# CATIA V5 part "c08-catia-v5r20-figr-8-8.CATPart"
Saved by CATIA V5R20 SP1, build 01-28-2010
Part number: Part1
Bounding box of the stored display mesh (mm): x 4.549 to 89.781, y -52.238 to 26.36, z 54 to 147.773
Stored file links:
  D:\v5_r20\psrt_files_downloaded\c08-catia-v5r20-prt\c08-catia-v5r20-figr-8-8.CATPart
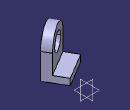
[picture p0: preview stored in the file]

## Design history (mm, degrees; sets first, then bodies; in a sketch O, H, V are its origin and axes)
Body1 (main body)
  Sketch1 on yz-plane, origin (0, 0, 0), H (0, 1, 0), V (0, 0, 1)
    point P1 (-104.4861, 0)
    line L1 (-104.4861, 0) -> (-104.4861, 44.267)
    arc A1 centre (-69.7903, 44.267) radius 34.6958 from (-104.4861, 44.267) to (-35.0946, 44.267) cw
    line L2 (-35.0946, 44.267) -> (-35.0946, 0)
    point P5 (-35.0946, 0)
    line L3 (-35.0946, 0) -> (-104.4861, 0)
    circle A2 centre (-69.7903, 44.267) radius 19.5413
    coincidence: P1 H, P5 H
    vertical: L1 V
    tangency: A1 L1, L2 A1
    horizontal: L3 H
  Pad1: profile Sketch1, direction (1, 0, 0), length 20
  Sketch2 on face of Pad1, origin (0, 0, 0), H (0, -1, 0), V (0, 0, 1)
    point P1 (35.0946, 0)
    line L1 (35.0946, 0) -> (104.4861, 0)
    line L2 (104.4861, 0) -> (104.4861, -15)
    line L3 (104.4861, -15) -> (35.0946, -15)
    line L4 (35.0946, -15) -> (35.0946, 0)
    reference projected line E1 (35.0946, 0) -> (35.0946, 44.267) from edge [face of Pad1 | face of Pad1]
    reference projected line E2 (104.4861, 44.267) -> (104.4861, 0) from edge [face of Pad1 | face of Pad1]
    distance L3 L1 = 15
    coincidence: P1 H, L4 E1, L2 E2
    horizontal: L1 H, L3 H
    vertical: L2 V, L4 V
  Pad2: profile Sketch2, direction (1, 0, 0), length 50
  Translate1: ToTransfor Pad2, Direction xy-plane, Length 69
  Rotate1: ToTransfor Translate1, Axis edge, Angle 121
